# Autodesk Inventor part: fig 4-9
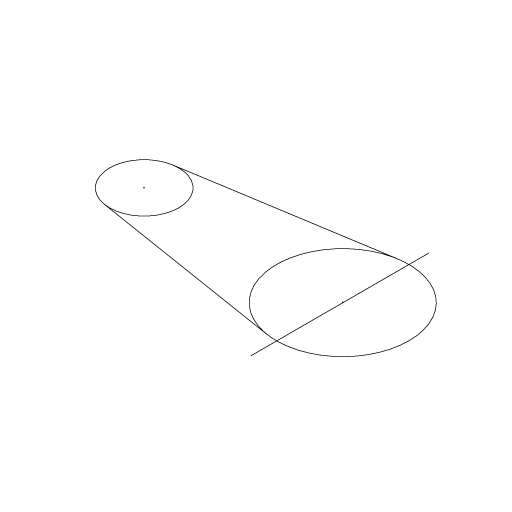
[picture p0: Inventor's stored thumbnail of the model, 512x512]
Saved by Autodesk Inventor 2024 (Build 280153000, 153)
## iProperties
Created: 2005-02
Part Number: fig 4-9
Document SubType Name: Modeling
Designer: CADCIM
Manufacturer: Standard
Standards Organization: Custom
Density: 1 g/cm^3
Material: Generic
Appearance: Default
Author: CADCIM
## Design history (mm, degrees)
sketch "Sketch1"
  geometry: L1 (-28.496, 15.735)-(10.446, 21.986); L2 (-28.503, 2.004)-(10.432, -4.291); L3 (12.58, 26.117)-(12.58, -9.642); A1 r 6.954 centre (-27.393, 8.869) between (-28.496, 15.735) and (-28.503, 2.004); A2 r 13.308 centre (12.555, 8.846) between (10.446, 21.986) and (10.432, -4.291)
  constraints: 6 end point, 4 point on circle, 4 tangent, 2 centre point, 1 vertical, 1 other
